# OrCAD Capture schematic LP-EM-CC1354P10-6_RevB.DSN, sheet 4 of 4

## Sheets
4 4_Mech: size A3
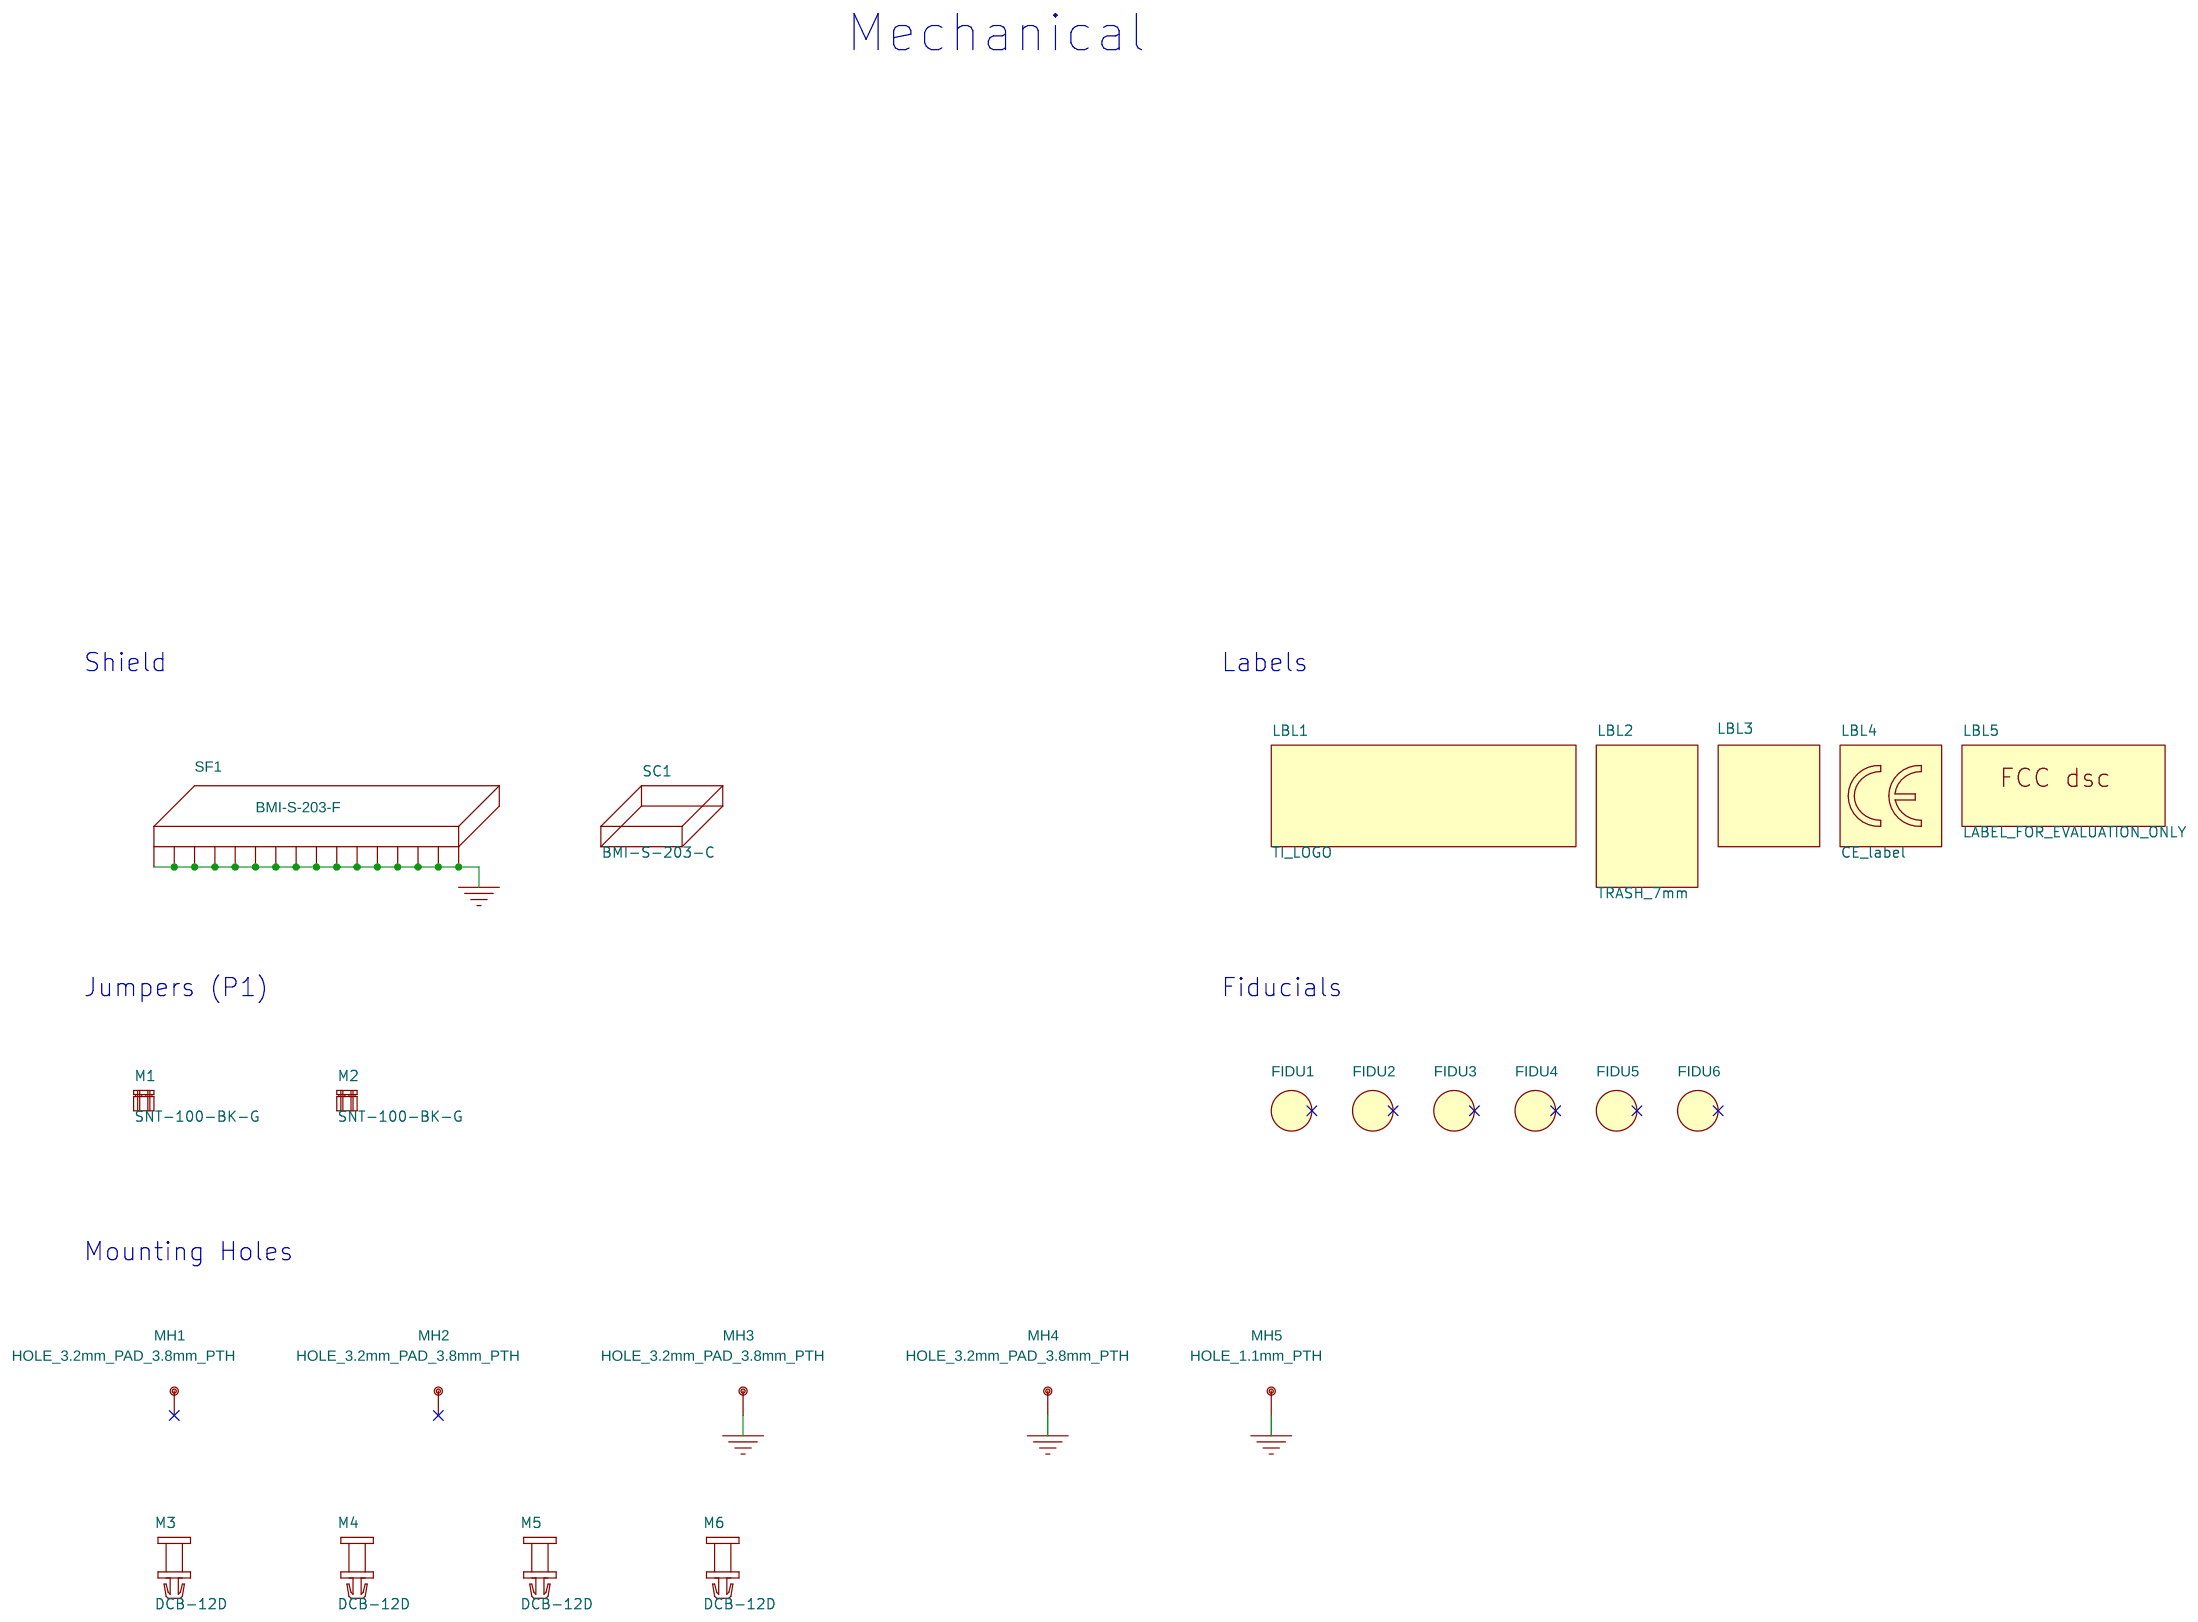
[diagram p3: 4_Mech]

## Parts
FIDU1  FIDU_1.27mm  [FID127X142]
FIDU2  FIDU_1.27mm  [FID127X142]
FIDU3  FIDU_1.27mm  [FID127X142]
FIDU4  FIDU_1.27mm  [FID127X142]
FIDU5  FIDU_1.27mm  [FID127X142]
FIDU6  FIDU_1.27mm  [FID127X142]
LBL1  TI_LOGO  [TI_LOGO_1]
LBL2  TRASH_7mm  [TRASH_7MM]
LBL3  ESD_LABEL_5x5mm  [ESD_LABEL_5X5]
LBL4  CE_label  [CE_MARKING]
LBL5  LABEL_FOR_EVALUATION_ONLY  [LABEL_FOR_EVALUATION_ONLY]
M1  SNT-100-BK-G  [SAMTEC_SNT100BKG]
M2  SNT-100-BK-G  [SAMTEC_SNT100BKG]
M3  DCB-12D  [MECH_DCB12D_A2B]
M4  DCB-12D  [MECH_DCB12D_A2B]
M5  DCB-12D  [MECH_DCB12D_A2B]
M6  DCB-12D  [MECH_DCB12D_A2B]
MH1  HOLE_3.2mm_PAD_3.8mm_PTH  [MTG320_380]
MH2  HOLE_3.2mm_PAD_3.8mm_PTH  [MTG320_380]
MH3  HOLE_3.2mm_PAD_3.8mm_PTH  [MTG320_380]
MH4  HOLE_3.2mm_PAD_3.8mm_PTH  [MTG320_380]
MH5  HOLE_1.1mm_PTH  [MTG110_170]
SC1  BMI-S-203-C  [MECH_BMIS203C_A]
SF1  BMI-S-203-F  [MECH_BMIS203F_A2N]

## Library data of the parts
FIDU1-FIDU6 = FIDMARK: NON COMPONENT, FIDUCIAL MARK, ROUND 1.27MM, SMD; Additional Datasheet URL: N/A; CLASS: IO; Country of Origin: Missing Info; Datasheet URL: N/A; Mass: N/A; Mounting Type: SMD; NOTEfied URL: https://notefied-dynamic-precision.com/NOTEfiedWebInterface/part/show?partNumber=19-00300; Packing Size: N/A; Packing Type: Missing Info; Part Number: 19-00300; Part Type: Non Component|FIDUCIAL; ROHS: Not Applicable; Revision: R032; Status: Released; Texas Part Status: Under Review; Type: Non Component; Vendor: NON_COMPONENT; Vendor Part Number: FIDUCIAL_1.27mm; Vendor Part Status: Active
LBL1 = TI_LOGO_V1: NON COMPONENT, LABEL, TEXAS INSTRUMENTS LOGO; Additional Datasheet URL: N/A; AutoDoc File: https://notefied-dynamic-precision.com/DB/Apps/Desktop/Item/Object.aspx?id=87770; BU Name: TEXAS INSTRUMENTS NORWAY; Country of Origin: Missing Info; Datasheet URL: N/A; Mass: N/A; Mounting Type: NOT APPLY; NOTEfied URL: https://notefied-dynamic-precision.com/NOTEfiedWebInterface/part/show?partNumber=19-00350; Notes: Custom Item; Packing Size: N/A; Packing Type: Missing Info; Part Number: 19-00350; Part Type: Non Component|LABEL; ROHS: Not Applicable; Revision: R035; Status: Released; Texas Part Status: Under Review; Type: Non Component; Vendor: NON_COMPONENT; Vendor Part Status: Active
LBL2 = TRASH_V2: NON COMPONENT, LABEL, TRASH 7mm; Additional Datasheet URL: N/A; Country of Origin: Missing Info; Datasheet URL: N/A; Mass: N/A; Mounting Type: NOT APPLY; NOTEfied URL: https://notefied-dynamic-precision.com/NOTEfiedWebInterface/part/show?partNumber=19-01044; Packing Size: N/A; Packing Type: Missing Info; Part Number: 19-01044; Part Type: Non Component|LABEL; ROHS: Not Applicable; Revision: R028; Status: Released; Texas Part Status: Under Review; Type: Non Component; Vendor: NON_COMPONENT; Vendor Part Status: Active
LBL3 = ESD_LABEL: NON COMPONENT, LABEL, ESD, 5 X 5 mm; Additional Datasheet URL: N/A; Country of Origin: Missing Info; Datasheet URL: N/A; Mass: N/A; Maximum Operating Temperature: N/A; Minimum Operating Temperature: N/A; Mounting Type: NOT APPLY; NOTEfied URL: https://notefied-dynamic-precision.com/NOTEfiedWebInterface/part/show?partNumber=19-00471; Packing Size: N/A; Packing Type: Missing Info; Part Number: 19-00471; Part Type: Non Component|LABEL; ROHS: Not Applicable; Revision: R013; Status: Released; Type: Non Component; Vendor: NON_COMPONENT; Vendor Part Status: Active
LBL4 = CE_LABEL_V1: NON COMPONENT, LABEL, CE; Additional Datasheet URL: N/A; Country of Origin: Missing Info; Datasheet URL: http://www.ce-marking.com/CE-marking-logo.html; Mass: N/A; Mounting Type: NOT APPLY; NOTEfied URL: https://notefied-dynamic-precision.com/NOTEfiedWebInterface/part/show?partNumber=19-00351; Packing Size: N/A; Packing Type: Missing Info; Part Number: 19-00351; Part Type: Non Component|LABEL; ROHS: Not Applicable; Revision: R035; Status: Released; Texas Part Status: Under Review; Type: Non Component; Vendor: NON_COMPONENT; Vendor Part Number: CE_LABEL; Vendor Part Status: Active
LBL5 = LABEL_FOR_EVALUATOIN_ONLY: NON COMPONENT, LABEL, FOR EVALUATION ONLY, NOT FCC APPROVED FOR RESALE; Additional Datasheet URL: N/A; AutoDoc File: https://notefied-dynamic-precision.com/DB/Apps/Desktop/Item/Object.aspx?id=115268; BU Name: TEXAS INSTRUMENTS NORWAY; Country of Origin: Missing Info; Datasheet URL: N/A; Mass: N/A; Maximum Operating Temperature: N/A; Minimum Operating Temperature: N/A; Mounting Type: NOT APPLY; NOTEfied URL: https://notefied-dynamic-precision.com/NOTEfiedWebInterface/part/show?partNumber=19-00830; Notes: Custom Item; Packing Size: N/A; Packing Type: Missing Info; Part Number: 19-00830; Part Type: Non Component|LABEL; REACH/SVHC Compliance: Missing Info; REACH/SVHC Details: N/A; REACH/SVHC Source: N/A; REACH/SVHC Status: Missing Info; ROHS: Not Applicable; Revision: R035; Status: Released; Texas Part Status: Under Review; Type: Non Component; Vendor: NON_COMPONENT; Vendor Part Status: Active
M1 M2 = MECH_SHUNT_JUMPER_V1: MECHANIC, SHUNT, CURRENT RATING 4.3A PER PIN, 2.54 X 5.08 X 6.1mm, BLACK; Additional Datasheet URL: https://www.samtec.com/products/snt-100-bk-g; AutoDoc File: https://notefied-dynamic-precision.com/DB/Apps/Desktop/Item/Object.aspx?id=104092; BU Name: DYNAMIC PRECISION GDANSK; Budget Currency: USD; Budget Price: 0.146; Budgetary Price: 0.19442 USD; Client Status: UNDER_REVIEW; Country of Origin: China,Costa Rica,Malaysia,Singapore,Taiwan,United States,Vietnam; Datasheet URL: https://suddendocs.samtec.com/catalog_english/snt.pdf; Datasheet URL 1: http://suddendocs.samtec.com/catalog_english/snt.pdf; Datasheet URL 2: http://suddendocs.samtec.com/prints/snt-100-xx-x-x-mkt.pdf; Lead Time: 9; Mass: 0.52432g; Max Oper Temp: +125DEGC; Maximum Operating Temperature: +125DEGC; Min Oper Temp: -55DEGC; Minimum Operating Temperature: -55DEGC; Mounting Type: NOT APPLY; NOTEfied URL: https://notefied-dynamic-precision.com/NOTEfiedWebInterface/part/show?partNumber=19-00498; Packing Size: 1; Packing Type: Bulk; Part Number: 19-00498; Part Type: Mechanic|SHUNT; REACH/SVHC Compliance: Compliant; REACH/SVHC Details: SVHC List Version Dec 17, 2015 (168); REACH/SVHC Source: Material Declaration; REACH/SVHC Status: Unaffected; REACH/SVHC_COMPLIANCE: COMPLIANT; REACH/SVHC_DETAILS: SVHC LIST VERSION Dec 17, 2015; REACH/SVHC_SOURCE: MATERIAL DECLARATION; REACH/SVHC_STATUS: UNAFFECTED; ROHS: Compliant; Rated Current: 4.3A; Revision: R040; RoHS Status: ROHS_COMPLIANT; Rtd Current: 4.3A; Status: Released; Texas Part Status: Under Review; Type: Mechanic; Vendor: SAMTEC; Vendor Part Status: Active; Weight: 0.11724g
M3-M6 = MECH_SPACERS_SUPPORT_V1: MECHANIC, ACCESSORY, SPACER SUPPORT, PCB DIA. 3mm, NYLON 66, NPTH; Additional Datasheet URL: https://www.kangyang-europe.com/product/pc-board-hardware/dcb-12d/; Country of Origin: Missing Info; Datasheet URL: https://www.kangyang-europe.com/wp-content/uploads/2020/02/DCB-HD.pdf; Maximum Operating Temperature: N/A; Minimum Operating Temperature: N/A; Mounting Type: NPTH; NOTEfied URL: https://notefied-dynamic-precision.com/NOTEfiedWebInterface/part/show?partNumber=13-07898; Notes: Custom libraries; Packing Size: 1000; Packing Type: Missing Info; Part Number: 13-07898; Part Type: Mechanic|ACCESSORY; REACH/SVHC Compliance: Missing Info; REACH/SVHC Source: N/A; REACH/SVHC Status: Missing Info; ROHS: Compliant; Revision: R007; Status: Released; Texas Part Status: Under Review; Type: Mechanic; Vendor: SUZHOU SOLY ELECTRICIAN; Vendor Part Status: Active
MH1-MH4 = HOLE_PTH: NON COMPONENT, HOLE 3.2mm, PLATED, PAD SIZE 3.8mm; Additional Datasheet URL: N/A; Country of Origin: Missing Info; Datasheet URL: N/A; Mass: N/A; Mounting Type: NOT APPLY; NOTEfied URL: https://notefied-dynamic-precision.com/NOTEfiedWebInterface/part/show?partNumber=19-00083; Packing Size: N/A; Packing Type: Missing Info; Part Number: 19-00083; Part Type: Non Component|HOLE|PLATED; ROHS: Missing Info; Revision: R020; Status: Released; Type: Non Component; Vendor: NON_COMPONENT; Vendor Part Status: Active
MH5 = HOLE_PTH: NON COMPONENT, HOLE 1.1mm, PLATED, PAD SIZE 1.7mm; Additional Datasheet URL: N/A; Country of Origin: Missing Info; Datasheet URL: N/A; Mass: N/A; Mounting Type: NOT APPLY; NOTEfied URL: https://notefied-dynamic-precision.com/NOTEfiedWebInterface/part/show?partNumber=19-00062; Packing Size: N/A; Packing Type: Missing Info; Part Number: 19-00062; Part Type: Non Component|HOLE|PLATED; ROHS: Missing Info; Revision: R007; Status: Released; Type: Non Component; Vendor: NON_COMPONENT; Vendor Part Number: HOLE_1.1mm_PLATED; Vendor Part Status: Active
SC1 = SHIELD_COVER: MECHANIC, COVER FOR SHIELD BMI-S-203; Additional Datasheet URL: https://www.laird.com/products/emi-and-non-emi-metallic/board-level-shielding-bls/two-piece-board-level-shields/bmi-s-203-c; Budgetary Price: 0.85209 USD; Country of Origin: Czech Republic; Datasheet URL: https://www.laird.com/sites/default/files/2023-08/bmi-s-203-sales.pdf; Lead Time: 4; Mass: N/A; Maximum Operating Temperature: N/A; Minimum Operating Temperature: N/A; Mounting Type: NOT APPLY; NOTEfied URL: https://notefied-dynamic-precision.com/NOTEfiedWebInterface/part/show?partNumber=13-00422; Packing Size: 300; Packing Type: Bulk; Part Number: 13-00422; Part Type: Mechanic|SHIELD; REACH/SVHC Compliance: Compliant; REACH/SVHC Details: SVHC List Version Jan 12, 2017 (173); REACH/SVHC Source: REACH Declaration; REACH/SVHC Status: Unaffected; ROHS: Compliant; Revision: R039; Status: Released; Texas Part Status: Under Review; Type: Mechanic; Vendor: LAIRD; Vendor Part Status: Active
SF1 = SHIELD_COVER_BMIS-203: MECHANIC, FRAME FOR SHIELD BMI-S-203, SMD; Additional Datasheet URL: https://www.laird.com/products/emi-and-non-emi-metallic/board-level-shielding-bls/two-piece-board-level-shields/bmi-s-203-f; Budgetary Price: 1.37655 USD; CLASS: IC; Country of Origin: Czech Republic; Datasheet URL: https://www.laird.com/sites/default/files/emi-cat-essentials-1213.pdf; Lead Time: 4; Mass: N/A; Maximum Operating Temperature: N/A; Minimum Operating Temperature: N/A; Mounting Type: SMD; NOTEfied URL: https://notefied-dynamic-precision.com/NOTEfiedWebInterface/part/show?partNumber=13-00133; Packing Size: 300; Packing Type: Tape & Reel; Part Number: 13-00133; Part Type: Mechanic|SHIELD; REACH/SVHC Compliance: Compliant; REACH/SVHC Details: SVHC List Version Jan 15, 2018 (181); REACH/SVHC Source: REACH Declaration; REACH/SVHC Status: Unaffected; ROHS: Compliant; Revision: R044; Status: Released; Texas Part Status: Under Review; Type: Mechanic; Vendor: LAIRD; Vendor Part Status: Active

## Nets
GND: MH3.1 MH4.1 MH5.1 SF1.1(GND) SF1.2(GND) SF1.3(GND) SF1.4(GND) SF1.5(GND) SF1.6(GND) SF1.7(GND) SF1.8(GND) SF1.9(GND) SF1.10(GND) SF1.11(GND) SF1.12(GND) SF1.13(GND) SF1.14(GND) SF1.15(GND) SF1.16(GND) ; also on sheet 1 2 3

Not connected (* = marked no-connect by the designer): FIDU1 1*; FIDU2 1*; FIDU3 1*; FIDU4 1*; FIDU5 1*; FIDU6 1*; MH1 1*; MH2 1*

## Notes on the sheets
sheet 4
- Mechanical
- Shield
- Labels
- Jumpers (P1)
- Fiducials
- Mounting Holes
